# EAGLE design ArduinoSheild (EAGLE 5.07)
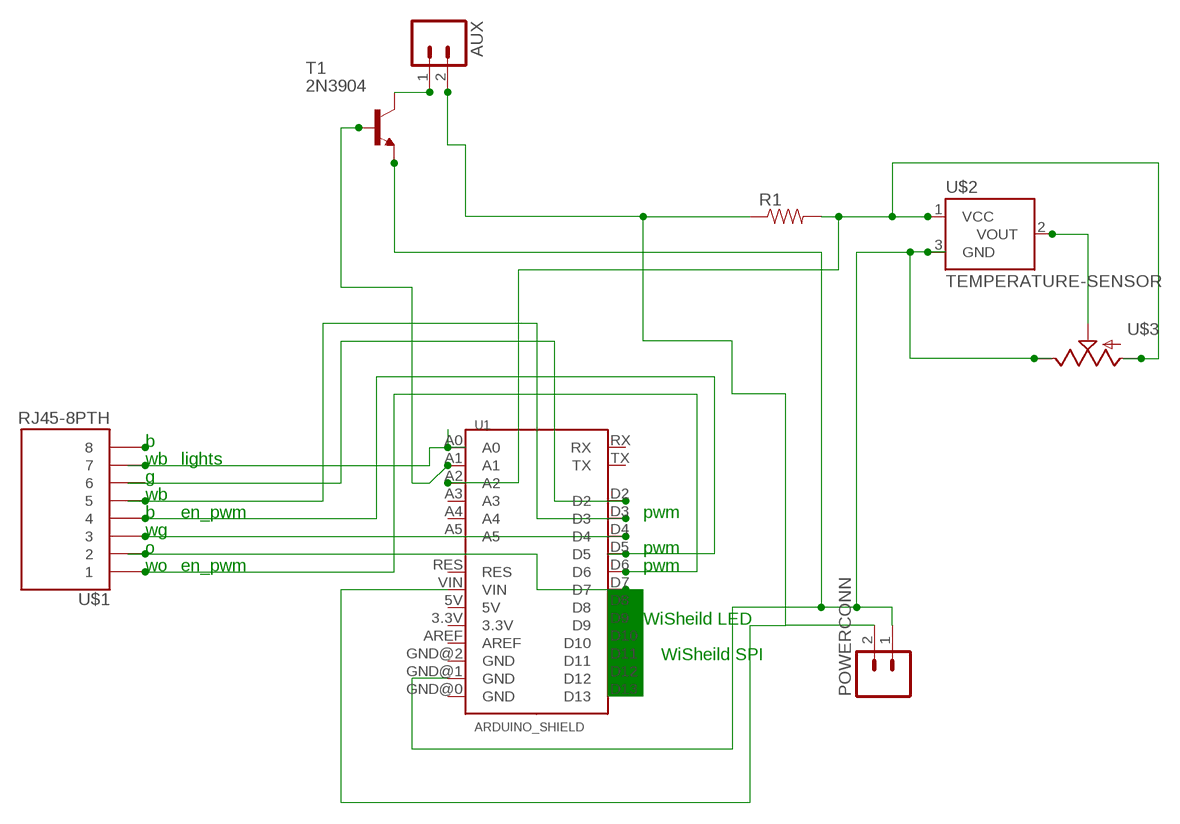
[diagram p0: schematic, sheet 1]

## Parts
AUX  M023.5MM  [SCREWTERMINAL-3.5MM-2]
POWERCONN  M023.5MM  [SCREWTERMINAL-3.5MM-2]
R1  RESISTORPTH1  [AXIAL-0.3]
T1  2N3904  [TO92]
U1  ARDUINO_SHIELD  [DUEMILANOVE_SHIELD]
U$1  RJ45-8PTH  [RJ45-8]
U$2  TEMPERATURE-SENSOR  [TO-92]
U$3  POTTRIM  [TRIM_POT]

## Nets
N$1: AUX.2 POWERCONN.2 R1.P$1 U1.VIN
N$2: POWERCONN.1 T1.3(E) U1.GND@1(GND) U$2.3(GND) U$3.2(E)
N$3: U1.D3 U$1.5
N$4: U1.D6 U$1.1
N$5: U1.D5 U$1.4
N$6: U1.D7 U$1.2
N$7: U1.D4 U$1.3
N$9: AUX.1 T1.1(C)
N$10: U1.A0 U$1.7
N$11: U$1.8
N$12: R1.P$2 U1.A2 U$2.1(VCC) U$3.3(A)
N$13: U$2.2(VOUT) U$3.1(S)
N$14: T1.2(B) U1.A1
N$16: U1.D2 U$1.6
Unconnected: U1.3.3V U1.5V U1.A3 U1.A4 U1.A5 U1.AREF U1.D8 U1.D9 U1.D10 U1.D11 U1.D12 U1.D13 U1.GND@0(GND) U1.GND@2(GND) U1.RES U1.RX U1.TX

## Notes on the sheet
- b
- wb | lights
- g
- wb
- b | en_pwm | pwm
- wg
- o | pwm
- wo | en_pwm | pwm
- WiSheild LED
- WiSheild SPI

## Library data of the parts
AUX POWERCONN = SparkFun:M02: Header 2
R1 = SparkFun:RESISTOR: Resistor
T1 = transistor:2N3904: NPN TRANSISTOR
U1 = SparkFun:ARDUINO_SHIELD
U$1 = SparkFun:RJ45-8: RJ45 Jack Simple RJ45, 8-pin connection - connector for common Cat5, Cat5e, and Cat6 Ethernet cables. Footprint not yet proven in production. Connector sku is PRT-00643; Breakout PCB sku is BOB-00716.
U$2 = SparkFun:TEMPERATURE-SENSOR
U$3 = SparkFun:POT

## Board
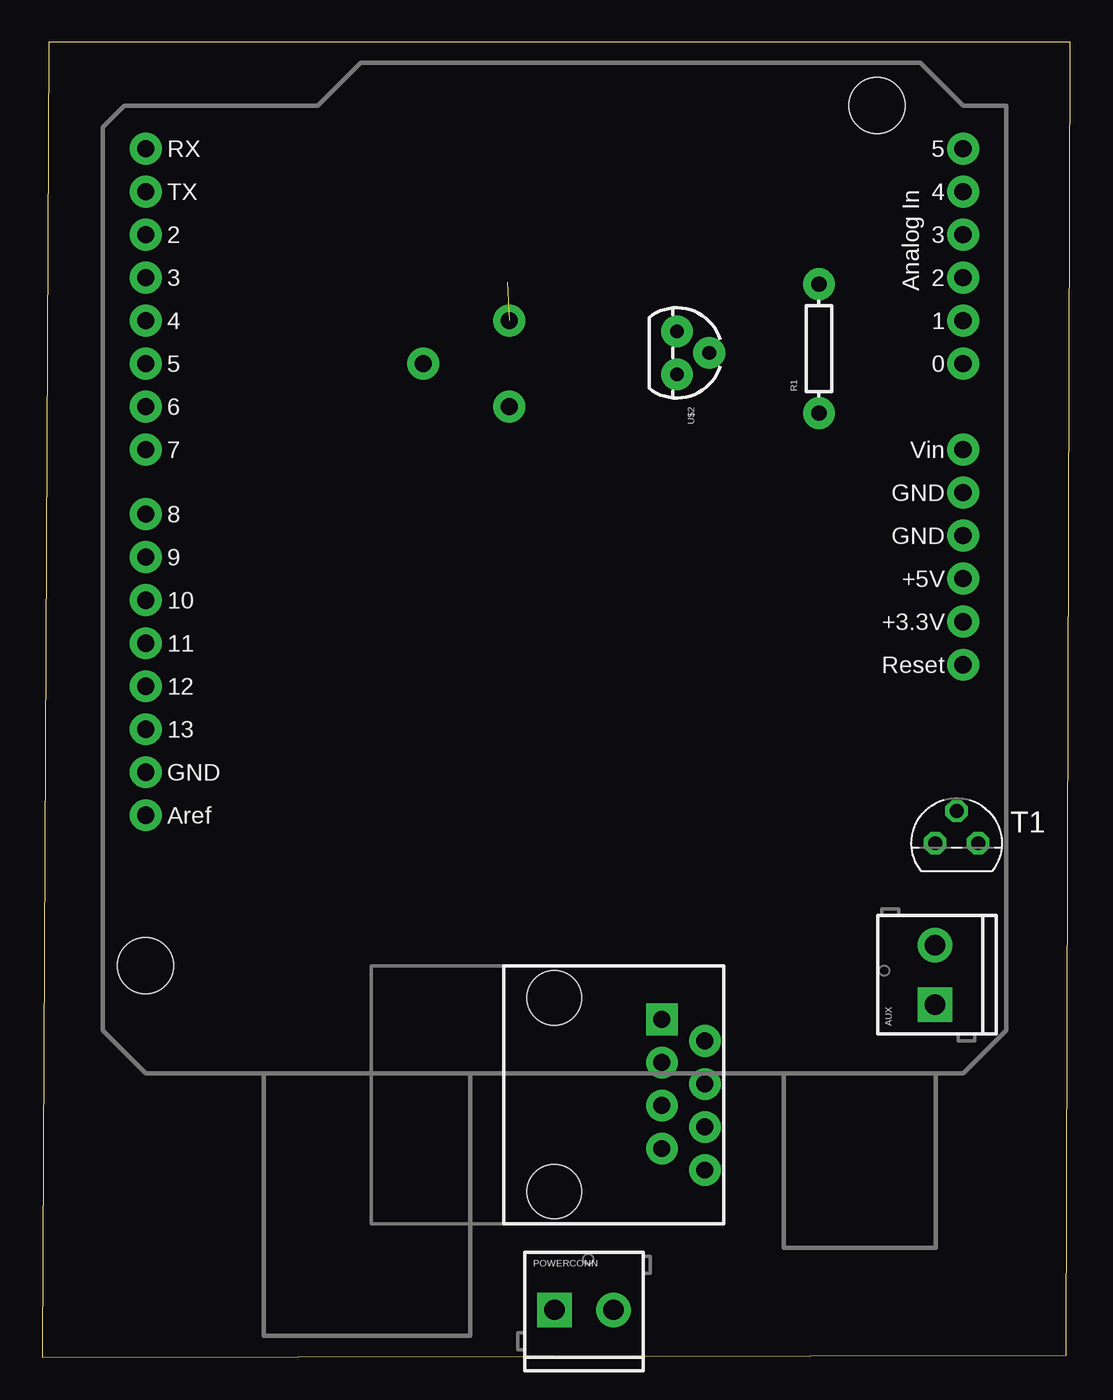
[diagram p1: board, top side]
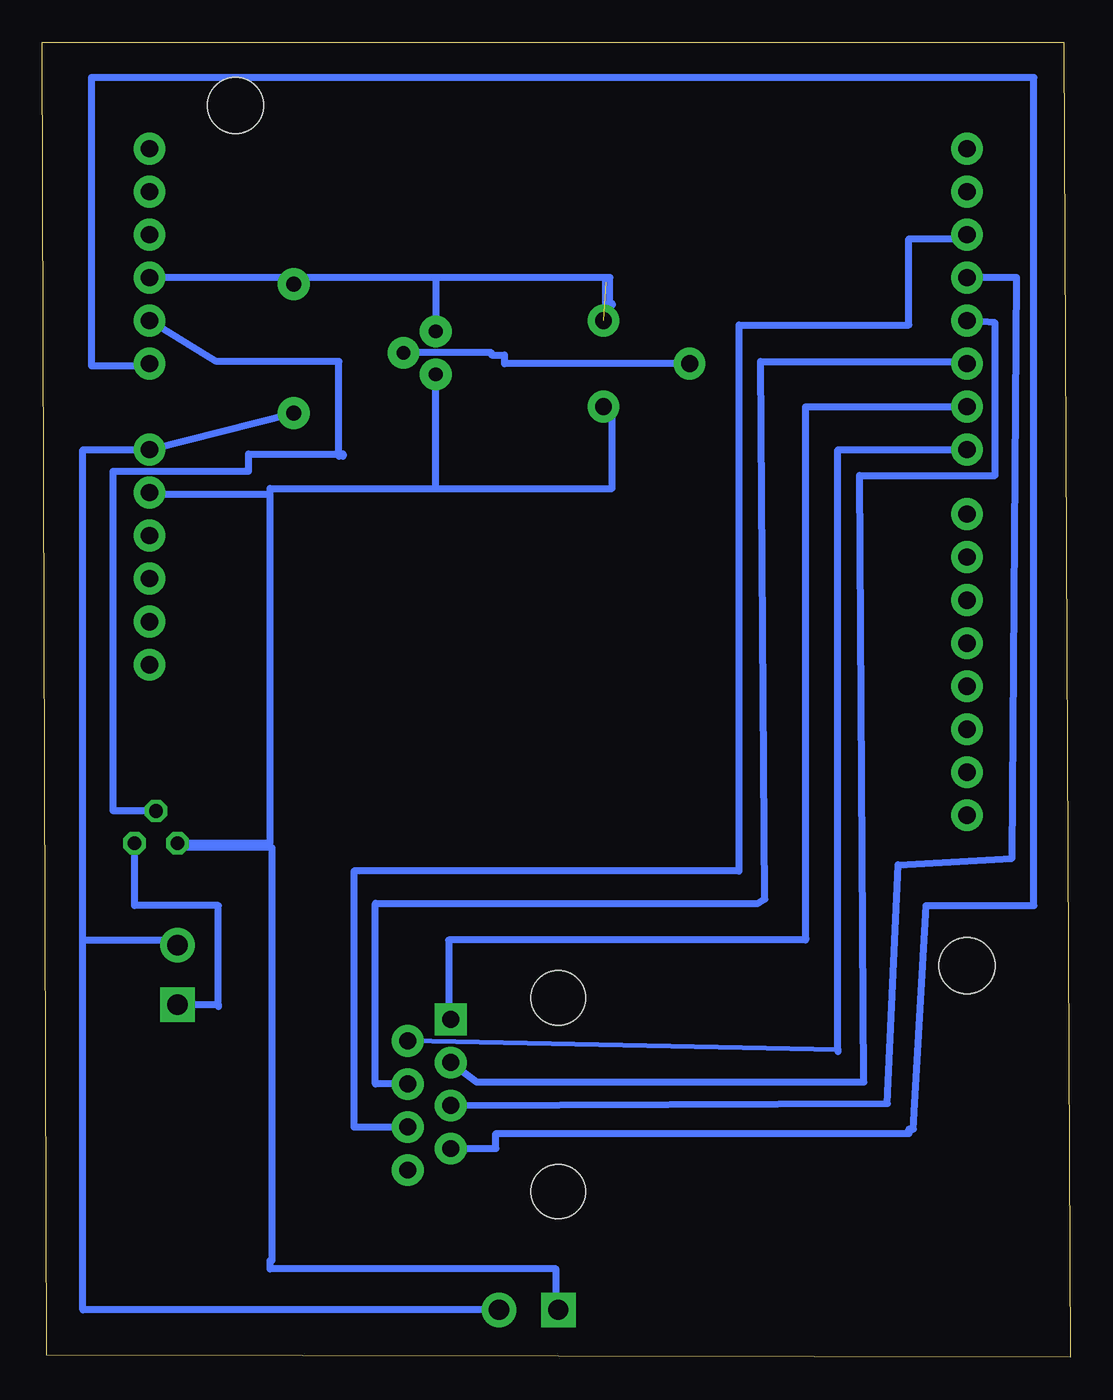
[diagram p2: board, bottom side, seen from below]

Size 60.69 x 77.65 mm. Coordinates in mm from the lower left corner, seen from the top.
Outline: 0,0 60.43,0.13 60.69,77.65 0.38,77.65 0,0
Copper layers (1*16): Top 0.035mm / dielectric 1.5mm / Bottom 0.035mm
Design rules "default": minimum track width 10mil, minimum drill 24mil, track to track 8mil, track to pad 8mil, pad to pad 8mil, via to via 8mil, smd to smd 8mil, copper to edge 40mil, drill to drill 8mil, minimum pad ring 10mil, minimum via ring 8mil, stop-mask expansion 4mil, vias tented up to drill 0mil, thermal gap 10mil

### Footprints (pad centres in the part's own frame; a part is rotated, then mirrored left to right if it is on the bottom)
SCREWTERMINAL-3.5MM-2 = drill 1.2 pad 2.032 square: 1 0,0 | drill 1.2 pad 2.032 round: 2 3.5,0
AXIAL-0.3 = drill 0.9 pad 1.88 round: P$1 -3.81,0; P$2 3.81,0
TO92 = drill 0.813 octagon: 1 1.27,0; 2 0,1.905; 3 -1.27,0
DUEMILANOVE_SHIELD = drill 1.016 pad 1.88 round: 3.3V 50.8,26.67; 5V 50.8,29.21; A0 50.8,41.91; A1 50.8,44.45; A2 50.8,46.99; A3 50.8,49.53; A4 50.8,52.07; A5 50.8,54.61; AREF 2.54,15.24; D2 2.54,49.53; D3 2.54,46.99; D4 2.54,44.45; D5 2.54,41.91; D6 2.54,39.37; D7 2.54,36.83; D8 2.54,33.02; D9 2.54,30.48; D10 2.54,27.94; D11 2.54,25.4; D12 2.54,22.86; D13 2.54,20.32; GND@0 50.8,31.75; GND@1 50.8,34.29; GND@2 2.54,17.78; RES 50.8,24.13; RX 2.54,54.61; TX 2.54,52.07; VIN 50.8,36.83 | hole 3.302: 45.72,57.15; 2.54,6.35
RJ45-8 = drill 1 pad 1.88 square: 1 -4.445,6.35 | drill 1 pad 1.88 round: 2 -3.175,8.89; 3 -1.905,6.35; 4 -0.635,8.89; 5 0.635,6.35; 6 1.905,8.89; 7 3.175,6.35; 8 4.445,8.89 | hole 3.2: -5.715,0; 5.715,0
TO-92 = drill 0.813 pad 1.88 round: 1 -1.27,0; 2 0,1.905; 3 1.27,0
TRIM_POT = drill 1 pad 1.88 round: 1 5.08,0; 2 0,2.54; 3 0,-2.54

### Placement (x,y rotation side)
AUX  52.7,20.83 90 top
POWERCONN  30.23,2.79 0 top
R1  45.85,59.56 90 top
T1  53.97,30.35 0 top
U1  3.56,16.76 0 top
U$1  30.23,15.49 270 top
U$2  37.47,59.31 270 top
U$3  27.56,58.67 180 top

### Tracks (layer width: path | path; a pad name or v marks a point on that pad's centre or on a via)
N$1
  Bottom 0.406: POWERCONN.2 58.29,2.79 58.29,24.64 | AUX.2 52.7,24.64 58.29,24.64 | R1.P$1 U1.VIN 58.29,53.59 58.29,24.64
N$2
  Bottom 0.406: POWERCONN.1 30.35,2.79 30.35,5.21 47.24,5.21 47.24,5.72 47.12,5.72 47.12,30.1 52.7,30.1 T1.3 47.24,30.35 47.24,50.93 | 47.24,50.93 54.36,50.93 U1.GND@1 | 27.05,56.13 27.05,51.31 37.47,51.31 | 27.05,56.13 27.05,56.39 | 37.47,51.31 47.24,51.31 47.24,50.93 | 37.47,51.31 U$2.3 | 27.05,56.13 U$3.2
N$3
  Bottom 0.406: U$1.5 10.8,14.99 10.16,29.08 3.43,29.46 3.18,63.75 U1.D3
N$4
  Bottom 0.406: U1.D6 15.62,56.13 15.62,24.77 15.62,24.64 36.7,24.64 36.7,19.94 U$1.1
N$5
  Bottom 0.406: U$1.4 41.02,16.13 41.02,26.8 18.41,26.8 18.03,27.05 18.29,58.8 6.1,58.8 U1.D5
N$6
  Bottom 0.305: 13.72,18.16 U$1.2
  Bottom 0.406: U1.D7 13.72,53.59 13.72,18.16 13.72,18.03
N$7
  Bottom 0.406: U$1.3 35.05,16.26 12.19,16.26 12.45,52.07 4.45,52.07 4.45,61.09 U1.D4
N$9
  Bottom 0.406: AUX.1 50.29,20.83 | 50.29,20.83 50.29,20.7 | 50.29,20.83 50.29,26.67 55.25,26.67 T1.1
N$10
  Bottom 0.406: U$1.7 33.91,12.32 33.91,13.21 9.53,13.21 9.53,13.46 9.27,13.46 8.51,26.67 2.16,26.67 2.16,75.56 57.78,75.56 57.78,58.55 54.36,58.55 U1.A0
N$12  (1 unrouted)
  Bottom 0.406: 45.85,63.75 U1.A2 | 37.47,63.75 27.18,63.75 27.18,61.47 27.31,61.47 27.31,62.23 27.05,62.23 27.05,62.1 27.43,62.1 27.43,63.5 | 37.47,63.75 45.85,63.75 | 45.85,63.75 R1.P$2 | 37.47,63.75 U$2.1
N$13
  Bottom 0.406: U$2.2 34.16,59.31 34.16,59.18 33.4,59.18 33.4,58.67 U$3.1
N$14
  Bottom 0.406: T1.2 56.52,32.26 56.52,52.32 48.51,52.32 48.51,53.34 42.93,53.34 42.93,53.21 43.18,53.21 43.18,58.8 50.42,58.8 U1.A1
N$16
  Bottom 0.406: U$1.6 42.29,13.59 42.29,28.7 19.56,28.7 19.56,60.96 9.53,60.96 9.53,66.04 6.1,66.04 U1.D2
